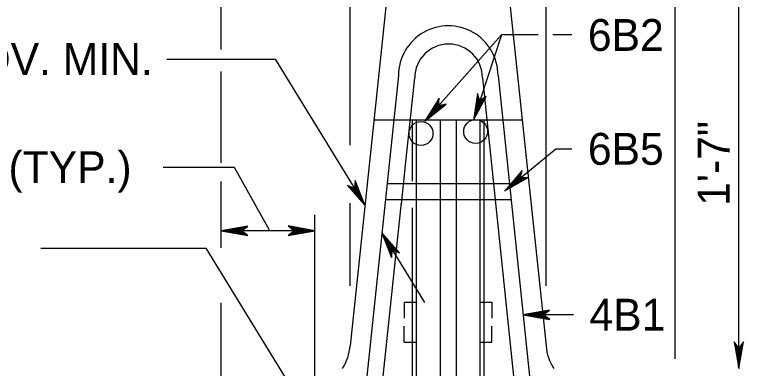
# Model space of a CAD drawing. Extents: x 499866 to 500993, y 499985 to 500645.
# Drawn here: x 500319.6 to 500411.1, y 500360.4 to 500404.9 of the extents above; entities that cross this region are included whole.
import ezdxf

# ---------------------------------------------------------------- set-up
doc = ezdxf.new("R2010")
doc.units = 0
for name, color, linetype in [('24', 7, 'Continuous'), ('5', 7, 'Continuous'), ('60', 7, 'Continuous')]:
    doc.layers.add(name, color=color, linetype=linetype)

msp = doc.modelspace()

# ---------------------------------------------------------------- linework, layer by layer
at = {"layer": '24'}
for points in [[(500377.249, 500391.587), (500378.851, 500394.588), (500378.04, 500394.011), (500377.729, 500394.936), (500377.249, 500391.587), (500377.312, 500391.801), (500378.781, 500394.512), (500378.014, 500393.954), (500377.731, 500394.794), (500377.34, 500391.918), (500377.39, 500392.019), (500378.635, 500394.346), (500378.009, 500393.937), (500377.762, 500394.648), (500377.406, 500392.068), (500377.425, 500392.178), (500378.519, 500394.211), (500378.008, 500393.912), (500377.76, 500394.468), (500377.524, 500392.486), (500377.584, 500392.666), (500378.386, 500394.076), (500378.006, 500393.875), (500377.793, 500394.296), (500377.61, 500392.693), (500377.675, 500392.859), (500378.241, 500393.932), (500377.949, 500393.786), (500377.808, 500394.094), (500377.716, 500393.019), (500377.785, 500393.174), (500378.138, 500393.814), (500377.948, 500393.752), (500377.839, 500393.993), (500377.796, 500393.262), (500378.047, 500393.673), (500377.905, 500393.648), (500377.846, 500393.884), (500377.816, 500393.38), (500377.985, 500393.648), (500377.849, 500393.557), (500377.837, 500393.716), (500377.881, 500393.547), (500377.921, 500393.615)], [(500371.147, 500391.48), (500373.814, 500393.592), (500372.84, 500393.387), (500372.923, 500394.359), (500371.147, 500391.48), (500371.29, 500391.65), (500373.719, 500393.551), (500372.793, 500393.345), (500372.868, 500394.228), (500371.362, 500391.747), (500371.448, 500391.82), (500373.519, 500393.456), (500372.781, 500393.332), (500372.839, 500394.082), (500371.483, 500391.858), (500371.544, 500391.952), (500373.359, 500393.379), (500372.771, 500393.309), (500372.765, 500393.918), (500371.758, 500392.194), (500371.884, 500392.335), (500373.183, 500393.309), (500372.754, 500393.276), (500372.726, 500393.746), (500371.919, 500392.349), (500372.045, 500392.476), (500372.992, 500393.235), (500372.666, 500393.217), (500372.66, 500393.555), (500372.147, 500392.606), (500372.271, 500392.721), (500372.851, 500393.167), (500372.652, 500393.186), (500372.648, 500393.451), (500372.317, 500392.798), (500372.711, 500393.074), (500372.571, 500393.108), (500372.611, 500393.347), (500372.382, 500392.897), (500372.644, 500393.076), (500372.483, 500393.047), (500372.536, 500393.198), (500372.509, 500393.025), (500372.572, 500393.071)], [(500381.162, 500382.738), (500387.597, 500387.997), (500389.602, 500387.997)], [(500381.162, 500382.738), (500384.108, 500384.386), (500383.121, 500384.339), (500383.356, 500385.279), (500381.162, 500382.738), (500381.329, 500382.883), (500384.008, 500384.362), (500383.068, 500384.305), (500383.281, 500385.158), (500381.415, 500382.966), (500381.511, 500383.023), (500383.798, 500384.3), (500383.055, 500384.294), (500383.23, 500385.02), (500381.551, 500383.055), (500381.625, 500383.138), (500383.628, 500384.249), (500383.041, 500384.274), (500383.132, 500384.871), (500381.874, 500383.342), (500382.019, 500383.46), (500383.446, 500384.208), (500383.02, 500384.244), (500383.067, 500384.709), (500382.055, 500383.468), (500382.199, 500383.573), (500383.247, 500384.166), (500382.924, 500384.2), (500382.972, 500384.533), (500382.319, 500383.684), (500382.46, 500383.777), (500383.097, 500384.122), (500382.905, 500384.172), (500382.943, 500384.432), (500382.516, 500383.844), (500382.946, 500384.053), (500382.814, 500384.109), (500382.891, 500384.337), (500382.596, 500383.932), (500382.881, 500384.066), (500382.718, 500384.062), (500382.793, 500384.202), (500382.74, 500384.037), (500382.81, 500384.072)], [(500363.628, 500380.91), (500362.409, 500384.004), (500362.324, 500383.034), (500361.439, 500383.389), (500363.628, 500380.91), (500363.509, 500381.093), (500362.42, 500383.903), (500362.35, 500382.978), (500361.546, 500383.299), (500363.439, 500381.187), (500363.396, 500381.289), (500362.452, 500383.69), (500362.36, 500382.964), (500361.675, 500383.231), (500363.37, 500381.331), (500363.299, 500381.415), (500362.479, 500383.517), (500362.378, 500382.948), (500361.806, 500383.115), (500363.133, 500381.685), (500363.037, 500381.842), (500362.495, 500383.334), (500362.404, 500382.923), (500361.956, 500383.03), (500363.033, 500381.879), (500362.951, 500382.033), (500362.51, 500383.134), (500362.434, 500382.824), (500362.116, 500382.914), (500362.858, 500382.165), (500362.786, 500382.314), (500362.533, 500382.982), (500362.459, 500382.801), (500362.21, 500382.873), (500362.727, 500382.379), (500362.58, 500382.825), (500362.509, 500382.704), (500362.296, 500382.809), (500362.653, 500382.468), (500362.56, 500382.763), (500362.541, 500382.604), (500362.415, 500382.696), (500362.569, 500382.622), (500362.544, 500382.695)], [(500363.628, 500380.91), (500362.409, 500384.004), (500362.324, 500383.034), (500361.439, 500383.389), (500363.628, 500380.91), (500363.509, 500381.093), (500362.42, 500383.903), (500362.35, 500382.978), (500361.546, 500383.299), (500363.439, 500381.187), (500363.396, 500381.289), (500362.452, 500383.69), (500362.36, 500382.964), (500361.675, 500383.231), (500363.37, 500381.331), (500363.299, 500381.415), (500362.479, 500383.517), (500362.378, 500382.948), (500361.806, 500383.115), (500363.133, 500381.685), (500363.037, 500381.842), (500362.495, 500383.334), (500362.404, 500382.923), (500361.956, 500383.03), (500363.033, 500381.879), (500362.951, 500382.033), (500362.51, 500383.134), (500362.434, 500382.824), (500362.116, 500382.914), (500362.858, 500382.165), (500362.786, 500382.314), (500362.533, 500382.982), (500362.459, 500382.801), (500362.21, 500382.873), (500362.727, 500382.379), (500362.58, 500382.825), (500362.509, 500382.704), (500362.296, 500382.809), (500362.653, 500382.468), (500362.56, 500382.763), (500362.541, 500382.604), (500362.415, 500382.696), (500362.569, 500382.622), (500362.544, 500382.695)], [(500357.323, 500377.724), (500353.973, 500378.316), (500354.773, 500377.724), (500353.99, 500377.141), (500357.323, 500377.724), (500357.1, 500377.718), (500354.067, 500378.272), (500354.836, 500377.717), (500354.125, 500377.187), (500356.98, 500377.707), (500356.869, 500377.724), (500354.27, 500378.186), (500354.853, 500377.717), (500354.254, 500377.262), (500356.818, 500377.724), (500356.706, 500377.707), (500354.435, 500378.117), (500354.877, 500377.724), (500354.426, 500377.315), (500356.383, 500377.707), (500356.194, 500377.707), (500354.603, 500378.033), (500354.913, 500377.733), (500354.579, 500377.4), (500356.16, 500377.724), (500355.981, 500377.734), (500354.785, 500377.939), (500355.015, 500377.707), (500354.766, 500377.478), (500355.817, 500377.724), (500355.648, 500377.741), (500354.93, 500377.878), (500355.048, 500377.717), (500354.853, 500377.538), (500355.561, 500377.724), (500355.092, 500377.835), (500355.16, 500377.707), (500354.954, 500377.579), (500355.443, 500377.707), (500355.135, 500377.784), (500355.264, 500377.683), (500355.116, 500377.622), (500355.263, 500377.717), (500355.187, 500377.733)], [(500345.582, 500377.724), (500348.932, 500377.132), (500348.132, 500377.724), (500348.915, 500378.307), (500345.582, 500377.724), (500345.804, 500377.73), (500348.838, 500377.176), (500348.069, 500377.731), (500348.78, 500378.261), (500345.925, 500377.74), (500346.036, 500377.724), (500348.635, 500377.262), (500348.052, 500377.731), (500348.651, 500378.185), (500346.087, 500377.723), (500346.198, 500377.74), (500348.47, 500377.33), (500348.028, 500377.723), (500348.479, 500378.132), (500346.522, 500377.741), (500346.711, 500377.74), (500348.302, 500377.415), (500347.992, 500377.714), (500348.325, 500378.047), (500346.745, 500377.724), (500346.924, 500377.713), (500348.119, 500377.509), (500347.889, 500377.741), (500348.139, 500377.97), (500347.088, 500377.724), (500347.257, 500377.707), (500347.975, 500377.57), (500347.857, 500377.731), (500348.052, 500377.91), (500347.344, 500377.723), (500347.813, 500377.612), (500347.745, 500377.74), (500347.95, 500377.869), (500347.462, 500377.741), (500347.769, 500377.664), (500347.64, 500377.765), (500347.788, 500377.825), (500347.641, 500377.731), (500347.718, 500377.714)], [(500365.757, 500377.441), (500366.976, 500374.347), (500367.06, 500375.317), (500367.946, 500374.962), (500365.757, 500377.441), (500365.876, 500377.259), (500366.965, 500374.448), (500367.034, 500375.373), (500367.839, 500375.052), (500365.946, 500377.164), (500365.989, 500377.062), (500366.933, 500374.661), (500367.025, 500375.387), (500367.711, 500375.12), (500366.015, 500377.02), (500366.086, 500376.936), (500366.906, 500374.834), (500367.007, 500375.403), (500367.578, 500375.236), (500366.252, 500376.666), (500366.348, 500376.509), (500366.89, 500375.017), (500366.981, 500375.428), (500367.429, 500375.321), (500366.351, 500376.472), (500366.434, 500376.318), (500366.875, 500375.217), (500366.951, 500375.527), (500367.269, 500375.437), (500366.527, 500376.186), (500366.599, 500376.037), (500366.852, 500375.369), (500366.926, 500375.55), (500367.175, 500375.478), (500366.657, 500375.972), (500366.804, 500375.526), (500366.877, 500375.647), (500367.089, 500375.542), (500366.732, 500375.883), (500366.825, 500375.588), (500366.844, 500375.747), (500366.969, 500375.655), (500366.816, 500375.729), (500366.841, 500375.656)], [(500383.457, 500367.181), (500386.807, 500366.589), (500386.007, 500367.181), (500386.79, 500367.764), (500383.457, 500367.181), (500383.68, 500367.187), (500386.714, 500366.633), (500385.945, 500367.188), (500386.655, 500367.718), (500383.8, 500367.197), (500383.911, 500367.181), (500386.51, 500366.719), (500385.927, 500367.188), (500386.527, 500367.642), (500383.963, 500367.18), (500384.074, 500367.197), (500386.345, 500366.787), (500385.904, 500367.18), (500386.355, 500367.589), (500384.397, 500367.198), (500384.586, 500367.197), (500386.177, 500366.872), (500385.867, 500367.171), (500386.201, 500367.504), (500384.62, 500367.181), (500384.799, 500367.17), (500385.995, 500366.966), (500385.765, 500367.198), (500386.014, 500367.427), (500384.963, 500367.181), (500385.132, 500367.164), (500385.85, 500367.027), (500385.732, 500367.188), (500385.927, 500367.367), (500385.219, 500367.18), (500385.688, 500367.069), (500385.62, 500367.197), (500385.826, 500367.326), (500385.337, 500367.198), (500385.645, 500367.121), (500385.516, 500367.222), (500385.664, 500367.282), (500385.517, 500367.188), (500385.594, 500367.171)], [(500410.532, 500360.436), (500411.125, 500363.786), (500410.532, 500362.986), (500409.949, 500363.769), (500410.532, 500360.436), (500410.527, 500360.658), (500411.081, 500363.692), (500410.525, 500362.923), (500409.995, 500363.634), (500410.516, 500360.779), (500410.532, 500360.89), (500410.994, 500363.489), (500410.526, 500362.906), (500410.071, 500363.505), (500410.533, 500360.941), (500410.516, 500361.052), (500410.926, 500363.324), (500410.533, 500362.882), (500410.124, 500363.333), (500410.515, 500361.376), (500410.516, 500361.565), (500410.842, 500363.156), (500410.542, 500362.846), (500410.209, 500363.179), (500410.532, 500361.599), (500410.543, 500361.778), (500410.748, 500362.973), (500410.515, 500362.743), (500410.286, 500362.993), (500410.532, 500361.942), (500410.55, 500362.111), (500410.687, 500362.829), (500410.525, 500362.711), (500410.346, 500362.906), (500410.533, 500362.198), (500410.644, 500362.667), (500410.516, 500362.599), (500410.387, 500362.804), (500410.515, 500362.316), (500410.593, 500362.623), (500410.491, 500362.494), (500410.431, 500362.642), (500410.525, 500362.495), (500410.542, 500362.572)]]:
    msp.add_lwpolyline(points, dxfattribs=at)
at = {"layer": '5'}
for p, q in [((500345.582, 500400.472), (500345.582, 500419.596)), ((500361.763, 500388.463), (500361.763, 500419.596)), ((500410.532, 500360.436), (500410.532, 500408.703)), ((500366.46, 500407.71), (500361.763, 500363.268)), ((500381.66, 500407.71), (500386.357, 500363.268)), ((500386.357, 500370.823), (500386.357, 500407.365)), ((500402.539, 500361.649), (500402.539, 500407.518)), ((500380.744, 500402.291), (500371.147, 500391.48)), ((500380.744, 500402.291), (500377.249, 500391.587)), ((500385.384, 500402.291), (500380.744, 500402.291)), ((500389.602, 500402.291), (500387.204, 500402.291)), ((500345.582, 500386.235), (500345.582, 500397.689)), ((500367.837, 500397.193), (500361.595, 500337.912)), ((500369.84, 500396.906), (500368.768, 500386.765)), ((500378.371, 500396.902), (500384.478, 500338.327)), ((500380.327, 500397.193), (500386.48, 500338.379)), ((500364.757, 500391.629), (500383.373, 500391.629)), ((500369.564, 500391.629), (500369.564, 500383.959)), ((500369.564, 500391.629), (500369.564, 500383.959)), ((500370.063, 500391.629), (500370.063, 500341.754)), ((500373.061, 500391.629), (500373.061, 500341.754)), ((500375.06, 500391.66), (500375.06, 500341.754)), ((500378.057, 500391.66), (500378.057, 500341.754)), ((500378.557, 500391.66), (500378.557, 500341.754)), ((500368.769, 500386.765), (500368.167, 500381.074)), ((500345.582, 500375.563), (500345.582, 500383.88)), ((500366.369, 500383.635), (500370.063, 500383.635)), ((500370.063, 500383.635), (500378.057, 500383.635)), ((500378.057, 500383.635), (500381.716, 500383.635)), ((500361.763, 500370.823), (500361.763, 500381.17)), ((500361.763, 500370.823), (500361.763, 500381.17)), ((500368.189, 500381.281), (500363.607, 500337.933)), ((500366.168, 500381.636), (500370.063, 500381.636)), ((500370.063, 500381.636), (500378.057, 500381.636)), ((500378.057, 500381.636), (500381.917, 500381.636)), ((500369.564, 500380.588), (500369.564, 500341.754)), ((500357.323, 500326.765), (500357.323, 500379.722)), ((500357.323, 500377.724), (500345.582, 500377.724)), ((500365.757, 500377.441), (500371.106, 500368.724)), ((500345.582, 500340.097), (500345.582, 500368.682)), ((500368.564, 500368.734), (500368.564, 500366.735)), ((500368.564, 500368.734), (500370.063, 500368.734)), ((500378.057, 500368.734), (500379.556, 500368.734)), ((500379.556, 500368.734), (500379.556, 500366.735)), ((500389.802, 500367.181), (500383.457, 500367.181)), ((500368.564, 500363.737), (500368.564, 500365.736)), ((500379.556, 500363.737), (500379.556, 500365.736)), ((500368.564, 500363.737), (500370.063, 500363.737)), ((500378.057, 500363.737), (500379.556, 500363.737))]:
    msp.add_line(p, q, dxfattribs=at)
for points in [[(500338.755, 500399.273), (500352.36, 500399.273), (500363.628, 500380.91)], [(500338.301, 500385.696), (500347.201, 500385.696), (500351.6, 500377.822)], [(500322.942, 500375.549), (500343.653, 500375.549), (500356.927, 500353.917)]]:
    msp.add_lwpolyline(points, dxfattribs=at)
for centre, radius, start, end in [((500374.082, 500397.193), 6.245, 359.93421, 180.02301), ((500374.124, 500396.902), 4.247, 0, 180), ((500355.785, 500363.726), 5.995, 326.72496, 355.62643), ((500392.335, 500363.726), 5.995, 184.37357, 213.27504)]:
    msp.add_arc(centre, radius, start, end, dxfattribs=at)
at = {"layer": '60'}
for centre in [(500370.659, 500389.926), (500377.517, 500390.176)]:
    msp.add_circle(centre, 1.499, dxfattribs=at)

# ---------------------------------------------------------------- texts
at = {"layer": '5'}
for s, p in [('6B2', (500391.602, 500400.291)), ('1 1/2" COV. MIN.', (500295.853, 500397.273)), ('6B5', (500391.602, 500385.997)), ('5 3/4" (TYP.)', (500303.602, 500383.696)), ('4B1', (500391.802, 500365.181))]:
    msp.add_text(s, height=4, dxfattribs=at).set_placement(p)
msp.add_text('1\'-7"', height=4, rotation=90, dxfattribs=at).set_placement((500409.389, 500380.844))

doc.saveas('drawing.dxf')
